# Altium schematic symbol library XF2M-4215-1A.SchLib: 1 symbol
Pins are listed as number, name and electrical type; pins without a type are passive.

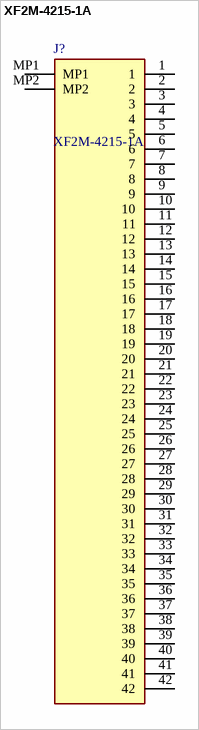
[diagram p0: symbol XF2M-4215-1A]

## XF2M-4215-1A
designator J?
FFC & FPC Connectors .5mm Rotary BackLock SMT Dual 42P Adhesv.; Manufacturer_Name: Omron Electronics; Geometry.Height: 3.2mm
footprint XF2M42151A
pins: 1, 2, 3, 4, 5, 6, 7, 8, 9, 10, 11, 12, 13, 14, 15, 16, 17, 18, 19, 20, 21, 22, 23, 24, 25, 26, 27, 28, 29, 30, 31, 32, 33, 34, 35, 36, 37, 38, 39, 40, 41, 42, MP1, MP2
